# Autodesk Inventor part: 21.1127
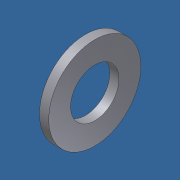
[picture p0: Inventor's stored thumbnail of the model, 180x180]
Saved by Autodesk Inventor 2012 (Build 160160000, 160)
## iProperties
Created: 2006-02
Part Number: 21.1127
Material: Steel, Mild
Description: M8 ROUND WASHER
Document SubType Name: Modeling
Standard: DIN 125
Designer: Andy Moles
Standards Organization: DIN
Language: en-US
Size Designation: A 8.4
Categories: <MemberInstance><Categories><Category DisplayName="Fasteners" InternalName="e4da775c-781d-43d5-af7c-5136215cf5a6" Mnemonic="FSTN"><Category DisplayName="Washers
Mass: 1.83162 g
Surface Area: 4.13936 cm^2
Volume: 0.233031 cm^3
Density: 7.86 g/cm^3
Vendor: S
Author: Andy Moles
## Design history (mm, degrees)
workaxis "Work Axis1"
workplane "Work Plane1"
body "Solid1"
sketch "Sketch"
  geometry: C1 r 8 at (0, 0); C2 r 4.2 at (0, 0); 1 further point
  constraints: 2 centre point, 2 coincident
  dimensions: "d0" = 8.4 diameter of C2 (= SD1); "d1" = 16 diameter of C1 (= SD2)
extrude "Body" new body sketch "Sketch" distance "d2" = 1.6 (= SD); taper "d3" = 0 deg
other parameters: "SD1" = 8.4 [user parameter; used in 1 equation term], "SD2" = 16 [user parameter; used in 1 equation term], "SD" = 1.6 [user parameter; used in 1 equation term], "d4" = 0, "d5" = 0, "d6" = 0, "d7" = 0, "NND" = 8 [user parameter]
